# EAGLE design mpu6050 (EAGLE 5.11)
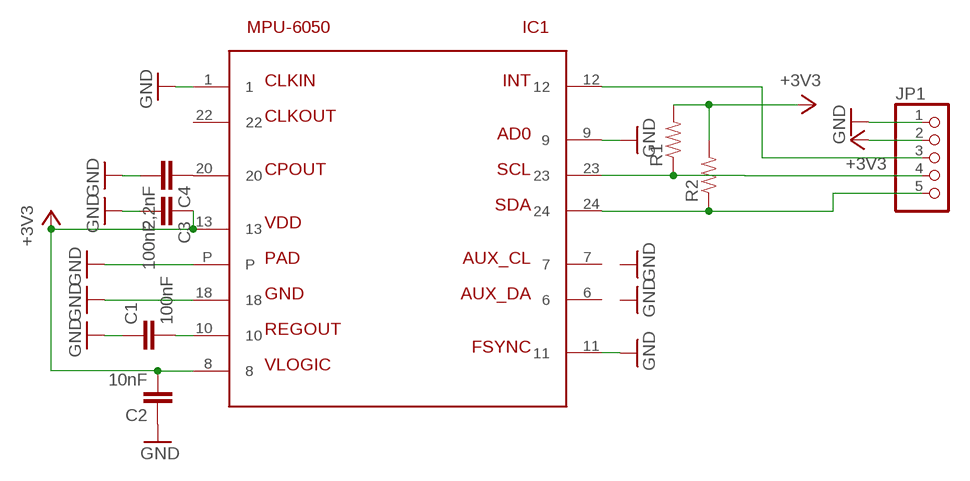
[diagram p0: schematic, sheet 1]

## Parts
C1  100nF  CAP0402-CAP  [0402-CAP]
C2  10nF  CAP0402-CAP  [0402-CAP]
C3  100nF  CAP0402-CAP  [0402-CAP]
C4  2,2nF  CAP0402-CAP  [0402-CAP]
IC1  MPU-6050  [QFN24]
JP1  PINHD-1X05_2.54  [1X05]
R1  RESISTOR0402-RES  [0402-RES]
R2  RESISTOR0402-RES  [0402-RES]

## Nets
+3V3: C2.2 C3.1 IC1.8 IC1.13 JP1.2 R1.2 R2.2
GND: C1.1 C2.1 C3.2 C4.2 IC1.1 IC1.9 IC1.11 IC1.18 IC1.P JP1.1
INT: IC1.12 JP1.3
N$2: C1.2 IC1.10
N$3: C4.1 IC1.20
SCL: IC1.23 JP1.4 R1.1
SDA: IC1.24 JP1.5 R2.1
Unconnected: IC1.6 IC1.7 IC1.22

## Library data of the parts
C1-C4 = SparkFun:CAP: Capacitor
IC1 = seb:MPU-6050
JP1 = pinhead-2:PINHD-1X05: PIN HEADER
R1 R2 = SparkFun:RESISTOR: Resistor

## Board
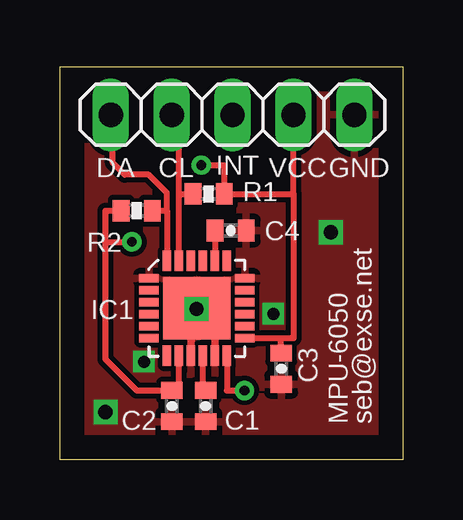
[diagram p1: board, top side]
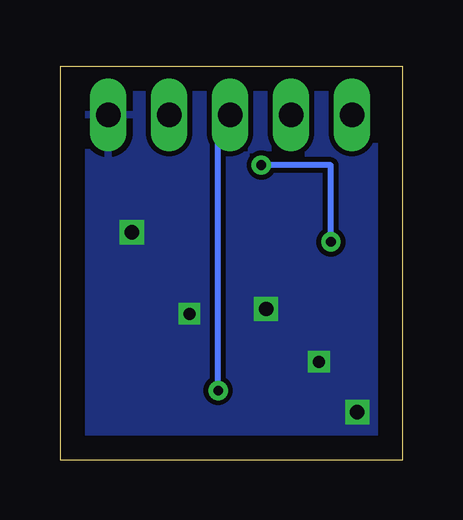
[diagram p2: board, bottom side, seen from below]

Size 14.3 x 16.4 mm. Coordinates in mm from the lower left corner, seen from the top.
Outline: 0,16.4 14.3,16.4 14.3,0 0,0 0,16.4
Copper layers (1*16): Top 0.035mm / dielectric 1.5mm / Bottom 0.035mm
Design rules "default *": minimum track width 10mil, minimum drill 0.4mm, track to track 8mil, track to pad 8mil, pad to pad 8mil, via to via 8mil, smd to smd 8mil, copper to edge 40mil, drill to drill 8mil, minimum pad ring 10mil, minimum via ring 8mil, stop-mask expansion 4mil, vias tented up to drill 0.6mm, thermal gap 10mil

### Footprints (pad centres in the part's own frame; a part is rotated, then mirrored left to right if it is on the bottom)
0402-CAP = smd 0.7 x 0.9: 1 -0.65,0; 2 0.65,0
QFN24 = smd 0.8 x 0.35: 1 -2,1.25; 2 -2,0.75; 3 -2,0.25; 4 -2,-0.25; 5 -2,-0.75; 6 -2,-1.25; 13 2,-1.25; 14 2,-0.75; 15 2,-0.25; 16 2,0.25; 17 2,0.75; 18 2,1.25 | smd 0.35 x 0.85: 7 -1.25,-1.975; 8 -0.75,-1.975; 9 -0.25,-1.975; 10 0.25,-1.975; 11 0.75,-1.975; 12 1.25,-1.975; 19 1.25,1.975; 20 0.75,1.975; 21 0.25,1.975; 22 -0.25,1.975; 23 -0.75,1.975; 24 -1.25,1.975 | smd 2.8 x 2.6: P 0,0
1X05 = drill 1.016 long: 1 -5.08,0; 2 -2.54,0; 3 0,0; 4 2.54,0; 5 5.08,0
0402-RES = smd 0.7 x 0.9: 1 -0.65,0; 2 0.65,0

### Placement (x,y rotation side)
C1  6.08,2.25 90 top
C2  4.67,2.25 90 top
C3  9.23,3.81 270 top
C4  7.12,9.57 0 top
IC1  5.71,6.33 0 top
JP1  7.2,14.4 180 top
R1  6.2,11.1 0 top
R2  3.2,10.4 180 top

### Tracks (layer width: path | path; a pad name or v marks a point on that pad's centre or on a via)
+3V3  (via drill 0.4)
  Top 0.254: IC1.8 4.96,2.95 C2.2 3.2,2.9 1.9,4.2 1.9,9.1 | 9.74,11.1 9.74,6.4 9.74,5.08 9.2,5.08 | 9.74,11.1 JP1.2 | R2.2 1.9,10.4 1.9,9.1 | 9.74,11.1 R1.2 6.85,12.3 v5.9,12.3 | 1.9,9.1 v3,9.1 | 9.2,5.08 IC1.13 | C3.1 9.2,4.46 9.2,5.08
  Bottom 0.254: v3,9.1 3,12.3 v5.9,12.3
GND  (via drill 0.5, 0.6)
  Top 0.305: IC1.11 6.46,6.3 v5.7,6.3 | IC1.9 5.46,6.3
  other vias: 11.3,9.5 1.9,2 3.5,4.1 8.9,6.1
  pour Bottom: 0,16.4 13.5,16.4 13.5,0 0,0
  pour Top: 0,16.4 13.5,16.4 13.5,0 0,0
INT  (via drill 0.4)
  Top 0.254: IC1.12 6.96,2.9 7.2,2.9 | 7.2,2.9 v7.7,2.9 7.2,2.9
  Bottom 0.254: JP1.3 7.7,13.9 v7.7,2.9
N$2
  Top 0.254: C1.2 5.96,2.85 IC1.10
N$3
  Top 0.254: IC1.20 6.46,9.67 C4.1
SCL
  Top 0.254: IC1.23 4.96,11.1 | 4.96,11.1 R1.1 | JP1.4 4.96,14.4 4.96,11.1
SDA
  Top 0.254: 4.46,10.4 IC1.24 | R2.1 4.46,10.4 | JP1.5 2.2,14.4 2.2,12.4 2.7,11.9 3.7,11.9 4.46,11.14 4.46,10.4

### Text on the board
tNames: DA | CL | INT | VCC | GND | MPU-6050 | seb@exse.net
